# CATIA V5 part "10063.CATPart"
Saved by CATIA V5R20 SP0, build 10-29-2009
Part number: CATPart1
Bounding box of the stored display mesh (mm): x 0 to 60, y 0 to 90, z -9.304 to 60
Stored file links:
  C:\Users\Raffaele\Desktop\3D X SITO CF\10063\10063.CATPart
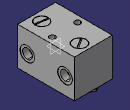
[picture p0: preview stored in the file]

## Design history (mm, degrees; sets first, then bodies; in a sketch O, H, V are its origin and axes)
Body1 (main body)
  Solid1 "10063": solid without history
